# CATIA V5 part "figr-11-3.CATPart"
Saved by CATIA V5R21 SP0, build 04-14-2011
Part number: Part1
Bounding box of the stored display mesh (mm): x -50 to 50, y -98.731 to 72.975, z 0 to 120
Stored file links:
  D:\CATIA V5R21 E-RESOURCES\CATIA-V5R21\catia-v5r21-prt\c11-catia-v5r21-prt\c11-catia-v5r21-figr-11-3.CATPart
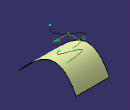
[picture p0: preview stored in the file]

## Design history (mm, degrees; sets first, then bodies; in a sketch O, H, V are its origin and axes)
Set1
  Sketch1 on yz-plane, origin (0, 0, 0), H (0, 1, 0), V (0, 0, 1)
    spline S1 through (-98.7309, 0) (-73.2816, 27.1192) (0, 74.8227) (72.975, 18.624)
    point P1 (-98.7309, 0)
    point P2 (0, 74.8227)
    coincidence: P1 H, P2 V
  Extrude1: Element1 Sketch1, Lim1 50, Lim2 50, Direction yz-plane
  Plane1: type Offset, RefPlane xy-plane, Offset 120
  Sketch2 on Plane1, origin (0, 0, 120), H (1, 0, 0), V (0, 1, 0)
    spline S1 through (28.7787, 44.6229) (-22.3035, 19.7059) (20.5049, -22.8447) (5.396, -48.9118)
  Project1: ToProject Sketch2, Support Extrude1
Body1 (main body)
